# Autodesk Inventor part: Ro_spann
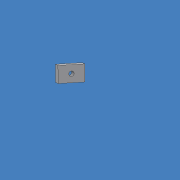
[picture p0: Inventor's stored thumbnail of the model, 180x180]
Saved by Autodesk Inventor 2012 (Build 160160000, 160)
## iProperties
Company: CAD-Verlag
Shininess: 64.0
Length Units: 11269
Angle Units: 11279
Time Units: 11290
Mass Units: 11283
Length Display Precision: 3
Angle Display Precision: 2
Compacted: True
Part Number: Ro_spann
Document SubType Name: Modeling
Created: 2004-09
Material: Standard
Designer: Greiling
Manufacturer: Standard
Standards Organization: Custom
Density: 1 g/cm^3
Density: 0.0
Volumn: 0.0
Area: 0.0
PropertySet Name: Model Information
Control State: 0
Master: False
Checked Out: False
Author: Jürgen Kronas
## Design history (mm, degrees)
sketch "Skizze1"
  geometry: L1 (0, 33.8)-(0, -2.6) reference; L2 (-4, 0)-(52, 0) reference; L3 (-4, 0)-(52, 0) reference; L4 (0, -2.6)-(0, 33.8) reference; L5 (0, 0)-(40, 0); L6 (40, 0)-(40, 26); L7 (40, 26)-(0, 26); L8 (0, 26)-(0, 0)
  constraints: 8 end point, 2 parallel, 1 horizontal, 1 perpendicular
  dimensions: "d0" = 40 distance of L6.end L7.end; "d1" = 26 distance of L5.end L6.end
extrude "Extrusion1" new body sketch "Skizze1" distance "d2" = 12; taper "d3" = 0 deg
sketch "Skizze2"
  geometry: L1 (0, 0)-(0, 26) reference; L2 (40, 0)-(0, 0) reference; 1 further point
  dimensions: "d4" = 20 distance from line of L1 point (20, 13); "d5" = 13 distance from line of L2 point (20, 13)
hole "Bohrung1" sketch "Skizze2" at (20, 13) diameter "d6" = 8.376; stored, may be unused: countersink angle "d10" = 82 deg, drill point angle "d12" = 118 deg; dims "d7" = 6, "d8" = 4, "d9" = 2, "d11" = 8
node "Volumenkörper1"
node "Volumenkörpern"
node "Oberflächenkörpern"
